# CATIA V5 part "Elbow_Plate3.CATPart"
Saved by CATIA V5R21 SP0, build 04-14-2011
Part number: Elbow_Plate3
Bounding box of the stored display mesh (mm): x -31.006 to 10.994, y -8.828 to -3.828, z 272.044 to 322.044
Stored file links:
  F:\教程\Robotic_Arm_Arduino_Kinect\机械臂CAD\Arm_Detailed_Design_Assembly\Elbow_Plate3.CATPart
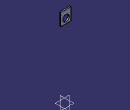
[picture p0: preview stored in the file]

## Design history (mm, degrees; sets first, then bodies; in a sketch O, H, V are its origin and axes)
Body1 (main body)
  DatumSurface1 to DatumSurface4
  Sketch1 on DatumSurface4, origin (0, -8.828, 0), H (-1, 0, 0), V (0, 0, 1)
    line L1 (-10.9938, 322.0436) -> (31.0062, 322.0436)
    line L2 (31.0062, 322.0436) -> (31.0062, 272.0436)
    line L3 (31.0062, 272.0436) -> (-10.9938, 272.0436)
    line L4 (-10.9938, 272.0436) -> (-10.9938, 322.0436)
    circle A1 centre (10.0062, 292.0436) radius 13
    point P5 (10.0062, 292.0436)
    length L1 = 42
    length L2 = 50
    radius A1 = 13
    distance P5 L1 = 30
    distance P5 L2 = 21
    horizontal: L1 H, L3 H
    vertical: L2 V, L4 V
  Pad1: profile Sketch1, direction (0, 1, 0), length 5
  Sketch2 on face of Pad1 from Sketch1.L2, origin (-31.0062, 0, 0), H (0, -1, 0), V (0, 0, 1)
    circle A1 centre (6.328, 307.0436) radius 1.25
    point P1 (6.328, 307.0436)
    circle A2 centre (6.328, 287.0436) radius 1.25
    point P2 (6.328, 287.0436)
    reference projected line E1 (8.828, 322.0436) -> (3.828, 322.0436) from edge [face of Pad1 from Sketch1.L1 | face of Pad1 from Sketch1.L2]
    reference projected line E2 (8.828, 272.0436) -> (8.828, 322.0436) from edge [start face of Pad1 | face of Pad1 from Sketch1.L2]
    reference projected line E3 (8.828, 272.0436) -> (8.828, 322.0436) from edge [start face of Pad1 | face of Pad1 from Sketch1.L2]
    reference projected line E4 (8.828, 272.0436) -> (3.828, 272.0436) from edge [face of Pad1 from Sketch1.L2 | face of Pad1 from Sketch1.L3]
    distance E1 P1 = 15
    radius A1 = 1.25
    distance E2 P1 = 2.5
    radius A2 = 1.25
    distance P2 E3 = 2.5
    distance P2 E4 = 15
  Pocket1: profile Sketch2, direction (1, 0, 0), length 4
  Sketch3 on face of Pad1 from Sketch1.L4, origin (10.9938, 0, 0), H (0, 1, 0), V (0, 0, 1)
    circle A1 centre (-6.328, 307.0436) radius 1.25
    point P1 (-6.328, 307.0436)
    circle A2 centre (-6.328, 287.0436) radius 1.25
    point P2 (-6.328, 287.0436)
    reference projected line E1 (-3.828, 322.0436) -> (-3.828, 272.0436) from edge [face of Pad1 from Sketch1.L4 | end face of Pad1]
    reference projected line E2 (-8.828, 322.0436) -> (-3.828, 322.0436) from edge [face of Pad1 from Sketch1.L4 | face of Pad1 from Sketch1.L1]
    reference projected line E3 (-8.828, 272.0436) -> (-3.828, 272.0436) from edge [face of Pad1 from Sketch1.L3 | face of Pad1 from Sketch1.L4]
    reference projected line E4 (-8.828, 322.0436) -> (-8.828, 272.0436) from edge [start face of Pad1 | face of Pad1 from Sketch1.L4]
    radius A1 = 1.25
    distance P1 E1 = 2.5
    distance P1 E2 = 15
    distance P2 E3 = 15
    distance P2 E4 = 2.5
    radius A2 = 1.25
  Pocket2: profile Sketch3, direction (-1, 0, 0), length 4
